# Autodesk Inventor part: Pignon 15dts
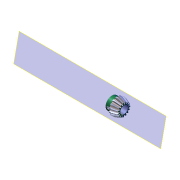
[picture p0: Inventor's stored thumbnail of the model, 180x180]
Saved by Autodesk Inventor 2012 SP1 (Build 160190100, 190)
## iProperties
Created: 2014-12
Part Number: Pignon 15dts
Material: Default
Document SubType Name: Modeling
Designer: Bruno
Density: 1 g/cm^3
Mass: 1.19463 g
Surface Area: 14.1625 cm^2
Volume: 1.19463 cm^3
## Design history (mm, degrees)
node "Pignon 15dts1"
node "Plan de construction1"
sketch "Esquisse3"
  geometry: L1 (16.279, -6.41)-(16.279, -4.886) reference; L2 (21.189, -8.381)-(16.279, -6.41) reference; L3 (24.399, -6.65)-(24.399, 6.65) reference; L4 (24.399, 0)-(15.145, 0); L5 (0.315, 0)-(0.315, -10.947); L6 (16.279, -5.648)-(23.841, -7.97); 2 further points
  constraints: 6 end point, 2 midpoint, 2 perpendicular, 4 other
  dimensions: "d6" = 17.0725 deg angle of L4 L6
feature "SrfRévolution2" sketch "Esquisse3" dims angle "d7" = 90 deg
node "Pignon 15dts"
node "Base1"
node "Boucle projetée1"
body "Srf3"
